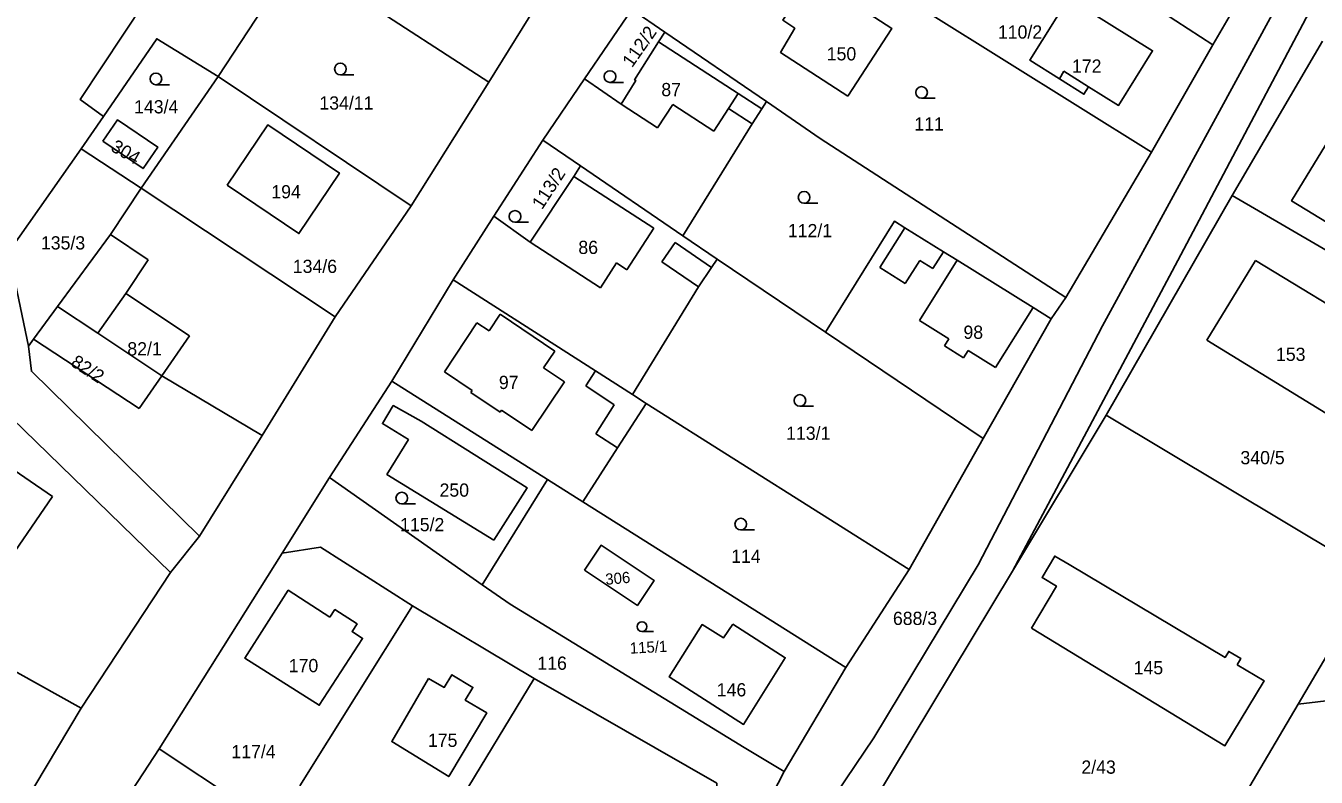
# Model space of a CAD drawing. Extents: x -747333 to -743907, y -1134120 to -1130051.
# Drawn here: x -746336.6 to -746170.7, y -1131825.9 to -1131729.3 of the extents above; entities that cross this region are included whole.
import ezdxf

# ---------------------------------------------------------------- set-up
doc = ezdxf.new("R2010")
doc.units = 0
for name, color, linetype in [('Hranice parcel', 7, 'Continuous'), ('Parcelní čísla', 7, 'Continuous'), ('Vnitřní kresba', 7, 'Continuous'), ('Značky kultur', 7, 'Continuous')]:
    doc.layers.add(name, color=color, linetype=linetype)

msp = doc.modelspace()

# ---------------------------------------------------------------- linework, layer by layer
at = {"layer": 'Hranice parcel'}
for p, q in [((-746183.97, -1131731.72), (-746211.35, -1131713.91)), ((-746183.97, -1131731.72), (-746175.84, -1131717.7)), ((-746301.83, -1131720.48), (-746311.89, -1131735.77)), ((-746301.83, -1131720.48), (-746277.08, -1131736.51)), ((-746277.08, -1131736.51), (-746267.83, -1131721.62)), ((-746258.71, -1131727.17), (-746264.78, -1131736.1)), ((-746258.71, -1131727.17), (-746254.46, -1131730.08)), ((-746220.28, -1131727.78), (-746191.89, -1131745.5)), ((-746254.46, -1131730.08), (-746255.26, -1131731.34)), ((-746241.4, -1131739.01), (-746254.46, -1131730.08)), ((-746191.89, -1131745.5), (-746183.97, -1131731.72)), ((-746169.89, -1131731.23), (-746181.5, -1131751.09)), ((-746311.89, -1131735.77), (-746321.79, -1131750.13)), ((-746287.07, -1131752.41), (-746311.89, -1131735.77)), ((-746287.07, -1131752.41), (-746277.08, -1131736.51)), ((-746264.78, -1131736.1), (-746270.15, -1131743.99)), ((-746260.09, -1131739.35), (-746264.78, -1131736.1)), ((-746243.25, -1131741.86), (-746242, -1131739.93)), ((-746242, -1131739.93), (-746241.4, -1131739.01)), ((-746326.66, -1131740.92), (-746329.53, -1131745.1)), ((-746252.15, -1131756.25), (-746243.25, -1131741.86)), ((-746329.53, -1131745.1), (-746338.81, -1131758.34)), ((-746321.79, -1131750.13), (-746329.53, -1131745.1)), ((-746270.15, -1131743.99), (-746276.43, -1131753.74)), ((-746270.15, -1131743.99), (-746265.3, -1131747.29)), ((-746202.88, -1131764.19), (-746191.89, -1131745.5)), ((-746266.18, -1131748.62), (-746271.78, -1131757.1)), ((-746265.3, -1131747.29), (-746266.18, -1131748.62)), ((-746252.15, -1131756.25), (-746265.3, -1131747.29)), ((-746296.84, -1131766.7), (-746321.79, -1131750.13)), ((-746181.5, -1131751.09), (-746197.7, -1131779.34)), ((-746146.31, -1131771.57), (-746181.5, -1131751.09)), ((-746296.84, -1131766.7), (-746287.07, -1131752.41)), ((-746276.43, -1131753.74), (-746281.7, -1131761.93)), ((-746271.78, -1131757.1), (-746276.43, -1131753.74)), ((-746247.71, -1131759.28), (-746252.15, -1131756.25)), ((-746338.81, -1131758.34), (-746336.31, -1131770.46)), ((-746248.44, -1131760.35), (-746247.71, -1131759.28)), ((-746247.71, -1131759.28), (-746233.81, -1131768.65)), ((-746178.52, -1131759.43), (-746184.77, -1131769.7)), ((-746281.7, -1131761.93), (-746289.58, -1131774.93)), ((-746281.7, -1131761.93), (-746263.38, -1131773.61)), ((-746204.77, -1131766.94), (-746207.1, -1131765.49)), ((-746204.77, -1131766.94), (-746202.88, -1131764.19)), ((-746306.23, -1131781.93), (-746296.84, -1131766.7)), ((-746213.53, -1131782.34), (-746204.77, -1131766.94)), ((-746233.81, -1131768.65), (-746213.53, -1131782.34)), ((-746263.38, -1131773.61), (-746258.62, -1131776.67)), ((-746297.6, -1131787.32), (-746289.58, -1131774.93)), ((-746289.58, -1131774.93), (-746269.53, -1131787.61)), ((-746256.85, -1131777.8), (-746258.62, -1131776.67)), ((-746318.01, -1131799.56), (-746340.04, -1131778.16)), ((-746260.53, -1131783.53), (-746256.85, -1131777.8)), ((-746256.85, -1131777.8), (-746223.05, -1131799.15)), ((-746197.7, -1131779.34), (-746209.77, -1131799.39)), ((-746163.29, -1131799.92), (-746197.7, -1131779.34)), ((-746314.31, -1131794.88), (-746306.23, -1131781.93)), ((-746264.99, -1131790.48), (-746260.53, -1131783.53)), ((-746223.05, -1131799.15), (-746213.53, -1131782.34)), ((-746297.6, -1131787.32), (-746303.67, -1131797.07)), ((-746277.93, -1131801.12), (-746297.6, -1131787.32)), ((-746269.53, -1131787.61), (-746277.93, -1131801.12)), ((-746269.53, -1131787.61), (-746264.99, -1131790.48)), ((-746264.99, -1131790.48), (-746231.2, -1131811.77)), ((-746314.31, -1131794.88), (-746318.01, -1131799.56)), ((-746303.67, -1131797.07), (-746319.5, -1131822.22)), ((-746329.51, -1131817), (-746318.01, -1131799.56)), ((-746231.2, -1131811.77), (-746223.05, -1131799.15)), ((-746209.77, -1131799.39), (-746228.3, -1131830.15)), ((-746329.51, -1131817), (-746357.15, -1131801.57)), ((-746173.02, -1131816.46), (-746163.91, -1131800.98)), ((-746301.39, -1131826.98), (-746286.89, -1131803.83)), ((-746286.89, -1131803.83), (-746271.26, -1131813.15)), ((-746231.2, -1131811.77), (-746239.12, -1131825.11)), ((-746271.26, -1131813.15), (-746289.03, -1131842.41)), ((-746182.24, -1131832.12), (-746173.02, -1131816.46)), ((-746338.17, -1131831.49), (-746329.51, -1131817)), ((-746319.5, -1131822.22), (-746332.13, -1131841.46)), ((-746319.5, -1131822.22), (-746308.91, -1131829.22)), ((-746243.86, -1131834.4), (-746239.12, -1131825.11))]:
    msp.add_line(p, q, dxfattribs=at)
for points in [[(-746209.77, -1131799.39), (-746188.47, -1131759.43), (-746165.71, -1131716.39), (-746153.65, -1131693.34), (-746142.41, -1131673.43), (-746130.42, -1131652.96), (-746119.1, -1131634.98), (-746122.9, -1131621.67)], [(-746154.22, -1131685.29), (-746175.35, -1131725.88), (-746198.19, -1131767.85), (-746214.17, -1131798.54), (-746227.58, -1131820.8), (-746249.27, -1131852.92), (-746268.11, -1131879.9), (-746296.61, -1131921.49), (-746301.25, -1131926.61)], [(-746312.93, -1131713.49), (-746329.64, -1131738.75), (-746326.66, -1131740.92)], [(-746230.93, -1131738.3), (-746225.29, -1131729.6), (-746235.61, -1131722.9), (-746236.77, -1131724.69), (-746237.95, -1131723.93), (-746239.73, -1131726.67), (-746238.56, -1131727.43), (-746239.28, -1131728.55), (-746237.75, -1131729.59), (-746239.58, -1131732.69), (-746230.93, -1131738.3)], [(-746199.96, -1131737.11), (-746200.56, -1131738.06), (-746203.72, -1131736.08), (-746207.52, -1131733.7), (-746202.54, -1131725.73), (-746191.73, -1131732.48), (-746196.12, -1131739.51), (-746199.96, -1131737.11)], [(-746326.66, -1131740.92), (-746319.8, -1131730.94), (-746311.89, -1131735.77)], [(-746255.26, -1131731.34), (-746258.34, -1131736.22), (-746258.18, -1131736.32), (-746260.09, -1131739.35)], [(-746241.4, -1131739.01), (-746234.47, -1131743.75), (-746202.88, -1131764.19)], [(-746162.14, -1131758.91), (-746157.95, -1131752.03), (-746162.91, -1131749), (-746159.44, -1131743.32), (-746165.34, -1131739.72), (-746168.15, -1131744.36), (-746169.01, -1131743.85), (-746173.86, -1131751.77), (-746162.14, -1131758.91)], [(-746326.74, -1131744.1), (-746324.84, -1131741.34), (-746319.67, -1131744.87), (-746321.55, -1131747.63), (-746326.74, -1131744.1)], [(-746310.74, -1131749.77), (-746301.51, -1131755.97), (-746296.31, -1131748.21), (-746305.53, -1131742.02), (-746310.74, -1131749.77)], [(-746321.79, -1131750.13), (-746325.74, -1131756.1), (-746332.56, -1131765.37)], [(-746223.6, -1131755.22), (-746224.93, -1131754.39), (-746233.81, -1131768.65)], [(-746207.1, -1131765.49), (-746216.88, -1131759.41), (-746218.64, -1131758.31), (-746223.6, -1131755.22)], [(-746258.62, -1131776.67), (-746250.13, -1131762.83), (-746248.44, -1131760.35)], [(-746184.77, -1131769.7), (-746169.46, -1131779.05), (-746163.11, -1131768.8), (-746178.52, -1131759.43)], [(-746332.56, -1131765.37), (-746335.63, -1131769.54), (-746336.31, -1131770.46)], [(-746332.56, -1131765.37), (-746327.38, -1131768.77), (-746319.13, -1131774.28), (-746306.23, -1131781.93)], [(-746336.31, -1131770.46), (-746335.91, -1131773.68), (-746314.31, -1131794.88)], [(-746276.46, -1131795.38), (-746290.19, -1131786.93), (-746287.43, -1131782.46), (-746290.77, -1131780.41), (-746289.39, -1131778.09), (-746285.79, -1131780.1), (-746272.16, -1131788.68), (-746276.46, -1131795.38)], [(-746173.02, -1131816.46), (-746145.54, -1131813.2), (-746104.87, -1131808.78), (-746061.62, -1131803.78), (-746009.82, -1131797.07), (-745872.32, -1131782.29)], [(-746303.67, -1131797.07), (-746298.76, -1131796.3), (-746286.89, -1131803.83)], [(-746264.81, -1131799.25), (-746262.65, -1131796.05), (-746255.85, -1131800.56), (-746257.99, -1131803.78), (-746264.81, -1131799.25)], [(-746180.84, -1131811.4), (-746180.38, -1131810.62), (-746181.95, -1131809.69), (-746182.41, -1131810.46), (-746202.46, -1131798.53), (-746204.31, -1131797.43), (-746205.95, -1131800.2), (-746204.11, -1131801.3), (-746207.33, -1131806.71)], [(-746297.53, -1131805.29), (-746302.88, -1131801.82), (-746308.48, -1131810.54), (-746298.9, -1131816.6), (-746293.33, -1131808.01), (-746294.67, -1131807.14), (-746294.04, -1131806.16), (-746296.89, -1131804.31), (-746297.53, -1131805.29)], [(-746239.12, -1131825.11), (-746244.27, -1131822.03), (-746274.35, -1131803.63), (-746277.93, -1131801.12)], [(-746245.72, -1131806.17), (-746246.91, -1131807.93), (-746249.68, -1131806.24), (-746253.9, -1131812.96), (-746244.34, -1131819.07), (-746238.97, -1131810.51), (-746245.72, -1131806.17)], [(-746207.33, -1131806.71), (-746182.44, -1131821.82), (-746177.39, -1131813.45), (-746180.84, -1131811.4)], [(-746284.86, -1131813.16), (-746289.57, -1131821.27), (-746282.24, -1131825.77), (-746277.35, -1131817.6), (-746280.12, -1131815.94), (-746279.15, -1131814.31), (-746281.85, -1131812.69), (-746282.82, -1131814.32), (-746284.86, -1131813.16)], [(-746271.26, -1131813.15), (-746247.77, -1131826.64), (-746247.79, -1131828.59)]]:
    msp.add_lwpolyline(points, dxfattribs=at)
at = {"layer": 'Vnitřní kresba'}
for p, q in [((-746255.26, -1131731.34), (-746245.02, -1131737.97)), ((-746203.13, -1131735.12), (-746203.72, -1131736.08)), ((-746199.96, -1131737.11), (-746203.13, -1131735.12)), ((-746245.02, -1131737.97), (-746246.27, -1131739.9)), ((-746245.02, -1131737.97), (-746242, -1131739.93)), ((-746255.39, -1131742.39), (-746260.09, -1131739.35)), ((-746253.43, -1131739.37), (-746255.39, -1131742.39)), ((-746248.15, -1131742.8), (-746253.43, -1131739.37)), ((-746246.27, -1131739.9), (-746248.15, -1131742.8)), ((-746243.25, -1131741.86), (-746246.27, -1131739.9)), ((-746266.18, -1131748.62), (-746255.89, -1131755.27)), ((-746255.89, -1131755.27), (-746259.35, -1131760.63)), ((-746223.6, -1131755.22), (-746226.83, -1131760.34)), ((-746325.74, -1131756.1), (-746320.9, -1131759.36)), ((-746262.74, -1131762.94), (-746271.78, -1131757.1)), ((-746254.84, -1131759.62), (-746253.15, -1131757.14)), ((-746253.15, -1131757.14), (-746248.44, -1131760.35)), ((-746219.99, -1131760.48), (-746218.64, -1131758.31)), ((-746320.9, -1131759.36), (-746323.76, -1131763.68)), ((-746260.69, -1131759.76), (-746262.74, -1131762.94)), ((-746259.35, -1131760.63), (-746260.69, -1131759.76)), ((-746250.13, -1131762.83), (-746254.84, -1131759.62)), ((-746226.83, -1131760.34), (-746223.56, -1131762.38)), ((-746223.56, -1131762.38), (-746221.68, -1131759.43)), ((-746216.88, -1131759.41), (-746221.71, -1131767.14)), ((-746221.68, -1131759.43), (-746219.99, -1131760.48)), ((-746323.76, -1131763.68), (-746327.38, -1131768.77)), ((-746315.57, -1131769.12), (-746323.76, -1131763.68)), ((-746211.93, -1131773.21), (-746207.1, -1131765.49)), ((-746277.06, -1131768.5), (-746275.64, -1131766.35)), ((-746275.64, -1131766.35), (-746268.61, -1131771.08)), ((-746221.71, -1131767.14), (-746217.93, -1131769.49)), ((-746282.81, -1131773.77), (-746278.63, -1131767.46)), ((-746278.63, -1131767.46), (-746277.06, -1131768.5)), ((-746322.04, -1131778.47), (-746335.63, -1131769.54)), ((-746319.13, -1131774.28), (-746315.57, -1131769.12)), ((-746217.93, -1131769.49), (-746218.51, -1131770.42)), ((-746218.51, -1131770.42), (-746216.05, -1131771.94)), ((-746268.61, -1131771.08), (-746270.05, -1131773.23)), ((-746216.05, -1131771.94), (-746215.47, -1131771.01)), ((-746215.47, -1131771.01), (-746211.93, -1131773.21)), ((-746279.22, -1131776.15), (-746282.81, -1131773.77)), ((-746270.05, -1131773.23), (-746267.36, -1131775.04)), ((-746263.38, -1131773.61), (-746264.62, -1131775.55)), ((-746319.13, -1131774.28), (-746322.04, -1131778.47)), ((-746267.36, -1131775.04), (-746271.57, -1131781.29)), ((-746279.39, -1131776.39), (-746279.22, -1131776.15)), ((-746275.62, -1131778.92), (-746279.39, -1131776.39)), ((-746264.62, -1131775.55), (-746260.97, -1131778.01)), ((-746275.46, -1131778.68), (-746275.62, -1131778.92)), ((-746271.57, -1131781.29), (-746275.46, -1131778.68)), ((-746260.97, -1131778.01), (-746263.35, -1131781.72)), ((-746263.35, -1131781.72), (-746260.53, -1131783.53))]:
    msp.add_line(p, q, dxfattribs=at)
msp.add_lwpolyline([(-746333.21, -1131789.79), (-746340.23, -1131799.97), (-746348.05, -1131794.58), (-746341.05, -1131784.42), (-746333.21, -1131789.79)], dxfattribs=at)
at = {"layer": 'Značky kultur'}
for p, q in [((-746296.183, -1131735.57), (-746294.433, -1131735.57)), ((-746319.903, -1131736.84), (-746318.153, -1131736.84)), ((-746261.513, -1131736.55), (-746259.763, -1131736.55)), ((-746221.443, -1131738.59), (-746219.693, -1131738.59)), ((-746236.553, -1131752.07), (-746234.803, -1131752.07)), ((-746273.723, -1131754.52), (-746271.973, -1131754.52)), ((-746237.093, -1131778.18), (-746235.343, -1131778.18)), ((-746288.283, -1131790.73), (-746286.533, -1131790.73)), ((-746244.693, -1131794.08), (-746242.943, -1131794.08)), ((-746257.404, -1131807.13), (-746255.934, -1131807.13))]:
    msp.add_line(p, q, dxfattribs=at)
for centre, radius in [((-746319.903, -1131736.09), 0.75), ((-746296.183, -1131734.82), 0.75), ((-746261.513, -1131735.8), 0.75), ((-746221.443, -1131737.84), 0.75), ((-746236.553, -1131751.32), 0.75), ((-746273.723, -1131753.77), 0.75), ((-746237.093, -1131777.43), 0.75), ((-746288.283, -1131789.98), 0.75), ((-746244.693, -1131793.33), 0.75), ((-746257.404, -1131806.5), 0.63)]:
    msp.add_circle(centre, radius, dxfattribs=at)

# ---------------------------------------------------------------- texts
at = {"layer": 'Parcelní čísla'}
for s, height, rotation, p in [('112/2', 1.7, 55, (-746258.673, -1131734.737)), ('304', 1.7, 330, (-746325.835, -1131745.268)), ('113/2', 1.7, 57, (-746270.247, -1131752.992)), ('82/2', 1.7, 327, (-746330.982, -1131772.882)), ('306', 1.436, 5, (-746262.047, -1131801.137)), ('115/1', 1.436, 3, (-746258.922, -1131809.987))]:
    msp.add_text(s, height=height, rotation=rotation, dxfattribs=at).set_placement(p)
for s, p in [('110/2', (-746211.63, -1131730.92)), ('150', (-746233.64, -1131733.72)), ('172', (-746202.104, -1131735.3)), ('87', (-746254.91, -1131738.32)), ('143/4', (-746322.71, -1131740.53)), ('134/11', (-746298.88, -1131740.04)), ('111', (-746222.37, -1131742.74)), ('194', (-746305.06, -1131751.45)), ('112/1', (-746238.64, -1131756.45)), ('135/3', (-746334.69, -1131758.02)), ('86', (-746265.58, -1131758.6)), ('134/6', (-746302.3, -1131761.04)), ('98', (-746216.06, -1131769.51)), ('82/1', (-746323.58, -1131771.64)), ('153', (-746175.87, -1131772.35)), ('97', (-746275.8, -1131775.96)), ('113/1', (-746238.86, -1131782.49)), ('340/5', (-746180.44, -1131785.63)), ('250', (-746283.43, -1131789.8)), ('115/2', (-746288.503, -1131794.24)), ('114', (-746245.93, -1131798.31)), ('688/3', (-746225.13, -1131806.29)), ('116', (-746270.85, -1131812.05)), ('170', (-746302.82, -1131812.36)), ('145', (-746194.17, -1131812.63)), ('146', (-746247.78, -1131815.47)), ('175', (-746284.93, -1131821.96)), ('117/4', (-746310.2, -1131823.42)), ('2/43', (-746200.89, -1131825.41))]:
    msp.add_text(s, height=1.7, dxfattribs=at).set_placement(p)

doc.saveas('drawing.dxf')
